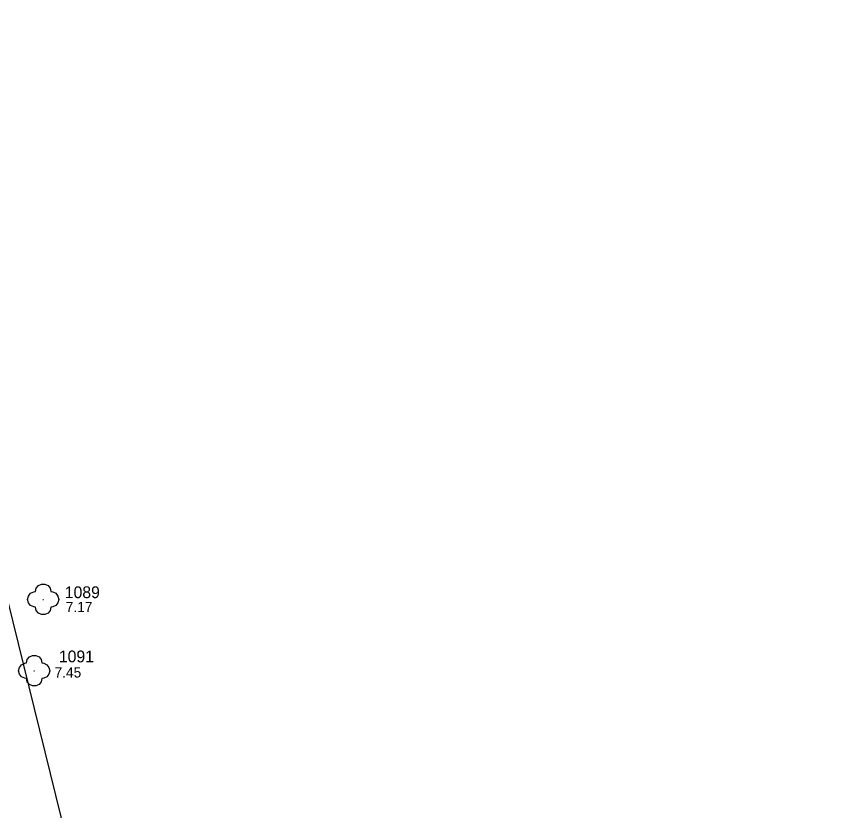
# Model space of a CAD drawing. Extents: x -792549 to -792339, y -1111914 to -1111617.
# Drawn here: x -792438.93 to -792412.17, y -1111801.86 to -1111776.27 of the extents above; entities that cross this region are included whole.
import ezdxf

# ---------------------------------------------------------------- set-up
doc = ezdxf.new("R2010")
doc.units = 0
for name, color, linetype in [('Vrstva 1', 7, 'Continuous'), ('Vrstva 41', 7, 'Continuous'), ('Vrstva 44', 7, 'Continuous'), ('Vrstva 48', 7, 'Continuous'), ('Vrstva 49', 7, 'Continuous'), ('Vrstva 50', 7, 'Continuous')]:
    doc.layers.add(name, color=color, linetype=linetype)

# ---------------------------------------------------------------- blocks, each defined once
blk = doc.blocks.new('SC6231')
at = {"layer": 'Vrstva 1'}
blk.add_line((0, 0), (0, 0), dxfattribs=at)
blk = doc.blocks.new('3$1300')
at = {"layer": 'Vrstva 1'}
for points in [[(20, 0), (19, -4.3), (16.2, -7.8), (12.2, -9.7), (10, -10), (9, -14.3), (6.2, -17.8), (2.2, -19.7), (-2.3, -19.7), (-6.3, -17.8), (-9.1, -14.3), (-10.1, -10), (-12.3, -9.7), (-16.3, -7.8), (-19.1, -4.3), (-20.1, 0), (-19.1, 4.3), (-16.3, 7.8), (-12.3, 9.7), (-10.1, 10), (-9.1, 14.3), (-6.3, 17.8), (-2.3, 19.7), (2.2, 19.7), (6.2, 17.8), (9, 14.3), (10, 10), (12.2, 9.7), (16.2, 7.8), (19, 4.3), (20, 0)], [(-0.5, 0), (0, 0), (0.5, 0)]]:
    blk.add_lwpolyline(points, dxfattribs=at)

msp = doc.modelspace()

# ---------------------------------------------------------------- linework, layer by layer
at = {"layer": 'Vrstva 41'}
msp.add_lwpolyline([(-792443.86, -1111776.27), (-792434.42, -1111814.6), (-792402.33, -1111815.45), (-792402.93, -1111822.06), (-792405.11, -1111832), (-792444.2, -1111829.87)], dxfattribs=at)

# ---------------------------------------------------------------- block references
at = {"layer": 'Vrstva 44', "xscale": 0.025, "yscale": 0.025000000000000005}
for p in [(-792438.07, -1111795.06), (-792438.36, -1111797.36)]:
    msp.add_blockref('3$1300', p, dxfattribs=at)
at = {"layer": 'Vrstva 48', "xscale": 0.1, "yscale": 0.10000000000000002}
for p in [(-792438.07, -1111795.06), (-792438.36, -1111797.36)]:
    msp.add_blockref('SC6231', p, dxfattribs=at)

# ---------------------------------------------------------------- texts
at = {"layer": 'Vrstva 49'}
for s, p in [('1089', (-792437.375, -1111795.02)), ('1091', (-792437.565, -1111797.09))]:
    msp.add_text(s, height=0.38, dxfattribs=at).set_placement(p)
at = {"layer": 'Vrstva 50'}
for s, p in [('7.17', (-792437.343, -1111795.47)), ('7.45', (-792437.703, -1111797.58))]:
    msp.add_text(s, height=0.33, dxfattribs=at).set_placement(p)

doc.saveas('drawing.dxf')
